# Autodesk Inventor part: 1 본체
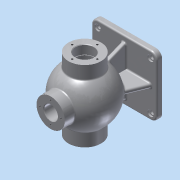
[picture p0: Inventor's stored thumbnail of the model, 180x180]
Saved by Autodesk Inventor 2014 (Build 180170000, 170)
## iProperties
Created: 2017-01
Part Number: 1 본체
Material: Aluminum 6061
Document SubType Name: Modeling
Designer: ksu
Density: 2.71 g/cm^3
Appearance: Aluminum - Flat
Mass: 1508.79 g
Surface Area: 1155.68 cm^2
Volume: 556.749 cm^3
Author: ksu
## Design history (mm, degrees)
sketch "Sketch1"
  geometry: L1 (-62.5, -57.5)-(62.5, -57.5); L2 (62.5, -57.5)-(62.5, 57.5); L3 (62.5, 57.5)-(-62.5, 57.5); L4 (-62.5, 57.5)-(-62.5, -57.5); L5 (-62.5, -57.5)-(62.5, 57.5); L6 (62.5, -57.5)-(-62.5, 57.5); 1 further point
  constraints: 12 end point, 2 midpoint, 2 parallel, 1 horizontal, 1 perpendicular
  dimensions: "d0" = 125 distance of L2.end L3.end; "d1" = 115 distance of L1.end L2.end
extrude "Extrusion1" new body sketch "Sketch1" distance "d2" = 10; taper "d3" = 0 deg
workplane "Work Plane1"
sketch "Sketch2"
  geometry: L1 (8.66, 52.288)-(-8.66, -52.288); A1 r 53 centre (0, 0) between (8.66, 52.288) and (-8.66, -52.288); 1 further point
  constraints: 2 end point, 2 point on circle, 1 centre point, 1 coincident, 1 midpoint
  dimensions: "d5" = 106 diameter of A1
revolve "Revolution1" sketch "Sketch2" stored, may be unused: angle "d6" = 90 deg
workplane "Work Plane2"
sketch "Sketch5"
  geometry: L1 (-62.5, 0)-(62.5, 0) reference; L2 (88.536, 85)-(-90.621, 85); L3 (0, 0)-(0, 119.622); C1 r 31 at (0, 85)
  constraints: 4 end point, 2 point on line, 1 centre point, 1 parallel, 1 perpendicular
  dimensions: "d18" = 85 distance between parallel lines of L1 L2; "d19" = 62 diameter of C1
extrude "Extrusion3" join sketch "Sketch5" distance "d20" = 136; taper "d21" = 0 deg
workplane "Work Plane3"
sketch "Sketch6"
  geometry: C1 r 27 at (0, 0); 1 further point
  constraints: 1 centre point, 1 coincident
  dimensions: "d23" = 54 diameter of C1
extrude "Extrusion4" join sketch "Sketch6" distance "d24" = 65; taper "d25" = 0 deg
sketch "Sketch8"
  geometry: L1 (-57.5, 0)-(-57.5, 10) reference; L2 (-57.5, 10)-(57.5, 10) reference; L3 (-42.988, 54)-(-68, 54) reference; L4 (-68, 54)-(-68, 116) reference; L5 (-68, 116)-(-42.988, 116) reference; L6 (-27, 130.607)-(-27, 150) reference; L7 (-27, 150)-(27, 150) reference; L8 (27, 150)-(27, 130.607) reference; L9 (42.988, 116)-(68, 116) reference; L10 (68, 116)-(68, 54) reference; L11 (68, 54)-(42.988, 54) reference; L12 (57.5, 10)-(57.5, 0) reference; L13 (57.5, 0)-(-57.5, 0) reference; L14 (0, 85)-(-68, 85); L15 (0, 85)-(68, 85); L16 (52, 103.5)-(50.25, 103.5); L17 (52, 102.5)-(68, 102.5); L18 (50.25, 103.5)-(50.25, 102.5); L19 (52, 103.5)-(52, 102.5); L20 (68, 85.456)-(68, 102.5); L21 (68, 102.5)-(68, 85); L22 (68, 85)-(68, 102.5); L23 (-68, 102.5)-(-68, 85); L24 (-68, 102.5)-(-68, 85); L25 (68, 102.5)-(68, 85.456); L26 (68, 102.5)-(68, 85); L27 (68, 102.5)-(70.625, 102.5); L28 (70.625, 102.5)-(70.625, 85); L29 (70.625, 85)-(68, 85); L30 (-68, 102.5)-(-39.278, 102.5); L31 (39.278, 102.5)-(50.25, 102.5); A1 r 53 centre (0, 85) between (0, 32) and (42.988, 54) reference; A2 r 53 centre (0, 85) between (42.988, 116) and (27, 130.607) reference; A3 r 43 centre (0, 85) between (39.278, 102.5) and (-39.278, 102.5); A4 r 53 centre (0, 85) between (-27, 130.607) and (-42.988, 116) reference; A5 r 53 centre (0, 85) between (-42.988, 54) and (0, 32) reference; 1 further point
  constraints: 36 end point, 7 perpendicular, 4 collinear, 4 parallel, 3 point on line, 2 midpoint, 2 point on circle, 1 centre point, 1 coincident
  dimensions: "d26" = 86 diameter of A3
revolve "Revolution2" sketch "Sketch8" stored, may be unused: angle "d31" = 90 deg
sketch "Sketch9"
  geometry: C1 r 27 at (0, 0) reference; 1 further point
  constraints: 1 coincident
hole "Hole1" sketch "Sketch9" at (0, 0) diameter "d32" = 26; stored, may be unused: countersink angle "d36" = 90 deg, drill point angle "d38" = 118 deg; dims "d33" = 6, "d34" = 4, "d35" = 2, "d37" = 50
sketch "Sketch12"
  geometry: L1 (62.5, 0)-(-62.5, 0) reference; L2 (-62.5, 0)-(-62.5, 10) reference; L3 (62.5, 10)-(-62.5, 10) reference; L4 (62.5, 0)-(62.5, 10) reference; L5 (13, 125.988)-(-13, 125.988) reference; L6 (52.5, 10)-(36.656, 49.214); L7 (-52.5, 10)-(-36.656, 49.214); L8 (0, 32)-(0, 33.772); L9 (-52.5, 10)-(52.5, 10); C1 r 17.5 at (0, 85) reference; C2 r 17.5 at (0, 85) reference; A1 r 53 centre (0, 85) between (-27, 130.607) and (27, 130.607) reference; A2 r 51.228 centre (0, 85) between (-36.656, 49.214) and (36.656, 49.214); 1 further point
  constraints: 8 end point, 4 point on circle, 1 centre point, 1 coincident
  dimensions: "d49" = 22 deg angle of L4 L6
extrude "Extrusion5" join sketch "Sketch12" stored distance "d50" = 8; taper "d51" = 0 deg
sketch "Sketch13"
  geometry: L1 (42.988, 116)-(68, 116) reference; L2 (68, 116)-(68, 102.5) reference; L3 (68, 102.5)-(52, 102.5) reference; L4 (52, 102.5)-(52, 103.5) reference; L5 (52, 103.5)-(50.25, 103.5) reference; L6 (50.25, 103.5)-(50.25, 102.5) reference; L7 (50.25, 102.5)-(39.278, 102.5) reference; L8 (13, 125.988)-(13, 150) reference; L9 (13, 150)-(27, 150) reference; L10 (27, 150)-(27, 130.607) reference; L11 (-68, 116)-(-42.988, 116) reference; L12 (-27, 130.607)-(-27, 150) reference; L13 (-27, 150)-(-13, 150) reference; L14 (-13, 150)-(-13, 125.988) reference; L15 (-39.278, 102.5)-(-68, 102.5) reference; L16 (-68, 102.5)-(-68, 116) reference; L17 (-42.988, 54)-(-68, 54) reference; L18 (-68, 54)-(-68, 67.5) reference; L19 (-68, 67.5)-(-39.278, 67.5) reference; L20 (39.278, 67.5)-(50.25, 67.5) reference; L21 (50.25, 67.5)-(50.25, 66.5) reference; L22 (50.25, 66.5)-(52, 66.5) reference; L23 (52, 66.5)-(52, 67.5) reference; L24 (52, 67.5)-(68, 67.5) reference; L25 (68, 67.5)-(68, 54) reference; L26 (68, 54)-(42.988, 54) reference; L27 (4, 32.151)-(4, 10) reference; L28 (4, 10)-(57.5, 10) reference; L29 (57.5, 10)-(57.5, 0) reference; L30 (57.5, 0)-(-57.5, 0) reference; L31 (-57.5, 0)-(-57.5, 10) reference; L32 (-57.5, 10)-(-4, 10) reference; L33 (-4, 10)-(-4, 32.151) reference; L34 (47.5, 10)-(47.5, 0); L35 (47.5, 10)-(32.63, 46.805); L36 (-47.5, 10)-(-32.63, 46.805); L37 (-47.5, 10)-(47.5, 10); A1 r 43 centre (0, 85) between (39.278, 102.5) and (13, 125.988) reference; A2 r 53 centre (0, 85) between (42.988, 116) and (27, 130.607) reference; A3 r 53 centre (0, 85) between (-27, 130.607) and (-42.988, 116) reference; A4 r 43 centre (0, 85) between (-13, 125.988) and (-39.278, 102.5) reference; A5 r 43 centre (0, 85) between (-39.278, 67.5) and (39.278, 67.5) reference; A6 r 53 centre (0, 85) between (4, 32.151) and (42.988, 54) reference; A7 r 53 centre (0, 85) between (-42.988, 54) and (-4, 32.151) reference; A8 r 50.235 centre (0, 85) between (-32.63, 46.805) and (32.63, 46.805); 1 further point
  constraints: 10 end point, 2 point on circle, 1 centre point, 1 coincident, 1 parallel, 1 perpendicular
  dimensions: "d52" = 10 distance between parallel lines of L29 L34; "d53" = 22 deg angle of L29 L35
extrude "Extrusion6" join sketch "Sketch13" stored distance "d54" = 8; taper "d55" = 0 deg
sketch "Sketch14"
  geometry: C1 r 27 at (0, 0) reference; A1 r 20 centre (0, 0) between (0, 20) and (20, 0); 2 further points
  constraints: 4 point on circle, 1 centre point, 1 coincident
  dimensions: "d56" = 40 diameter of A1
hole "Hole2" sketch "Sketch14" at (20, 0), (0, 20), (-20, 0), (0, -20) diameter "d57" = 3.459; stored, may be unused: countersink angle "d61" = 90 deg, drill point angle "d63" = 118 deg; dims "d58" = 9, "d59" = 4, "d60" = 2, "d62" = 11
sketch "Sketch15"
  geometry: C1 r 31 at (0, 0) reference; A1 r 24 centre (0, 0) between (0, 24) and (24, 0); 3 further points
  constraints: 4 point on circle, 1 centre point, 1 coincident
  dimensions: "d64" = 48 diameter of A1
hole "Hole3" sketch "Sketch15" at (0, -24), (24, 0), (0, 24), (-24, 0) diameter "d65" = 3.459; stored, may be unused: countersink angle "d69" = 90 deg, drill point angle "d71" = 118 deg; dims "d66" = 16, "d67" = 4, "d68" = 2, "d70" = 19
sketch "Sketch16"
  geometry: C1 r 31 at (0, 0) reference; A1 r 22.5 centre (0, 0) between (0, 22.5) and (22.5, 0); 3 further points
  constraints: 4 point on circle, 1 centre point, 1 coincident
  dimensions: "d72" = 45 diameter of A1
hole "Hole4" sketch "Sketch16" at (0, -22.5), (22.5, 0), (0, 22.5), (-22.5, 0) diameter "d73" = 3.459; stored, may be unused: countersink angle "d77" = 90 deg, drill point angle "d79" = 118 deg; dims "d74" = 12, "d75" = 4, "d76" = 2, "d78" = 15
fillet "Fillet1" dims "d80" = 12
sketch "Sketch17"
  geometry: A1 r 12 centre (-50.5, 45.5) between (-50.5, 57.5) and (-62.5, 45.5) reference; A2 r 12 centre (-50.5, -45.5) between (-62.5, -45.5) and (-50.5, -57.5) reference; A3 r 12 centre (50.5, -45.5) between (50.5, -57.5) and (62.5, -45.5) reference; A4 r 12 centre (50.5, 45.5) between (62.5, 45.5) and (50.5, 57.5) reference; 5 further points
  constraints: 4 coincident
hole "Hole5" sketch "Sketch17" at (-50.5, 45.5), (50.5, 45.5), (-50.5, -45.5), (50.5, -45.5) diameter "d81" = 8; stored, may be unused: countersink angle "d85" = 90 deg, drill point angle "d87" = 118 deg; dims "d82" = 12, "d83" = 12, "d84" = 3, "d86" = 10
chamfer "Chamfer1" distance "d88" = 1; stored, may be unused: second distance "d89" = 2, angle "d90" = 45 deg
fillet "Fillet2" dims "d91" = 3
fillet "Fillet3" dims "d92" = 3
fillet "Fillet4" dims "d93" = 3
fillet "Fillet5" dims "d94" = 3
workplane "Work Plane5"
sketch "Sketch19"
  geometry: L1 (0, 0)-(0, 184.171); L2 (27, 150)-(27, 132.286) reference; L3 (-27, 150)-(27, 150) reference; L4 (35.897, 140)-(-32.574, 140); L5 (-20.739, 143.002)-(20.739, 143.002); L6 (20.739, 143.002)-(20.739, 136.998); L7 (20.739, 136.998)-(-20.739, 136.998); L8 (-20.739, 136.998)-(-20.739, 143.002); 1 further point
  constraints: 4 end point, 2 point on line, 1 parallel, 1 vertical, 2 other
  dimensions: "d100" = 10 distance between parallel lines of L3 L4
emboss "Emboss2" sketch "Sketch19" dims "d0" = 125, "d1" = 115, "d20" = 136, "d101" = 0.5, "d102" = 0
body "Solid1"
node "Projected Loop4"
node "Projected Loop5"
node "Project Cut Edges1"
node "Project Cut Edges2"
other parameters: "d4" = 85, "d11" = 4, "d12" = 4, "d13" = 4, "d14" = 4, "d17" = 68, "d27" = 17.5, "d28" = 16, "d29" = 18.5, "d30" = 1.75, "d41" = 106, "d45" = 106
